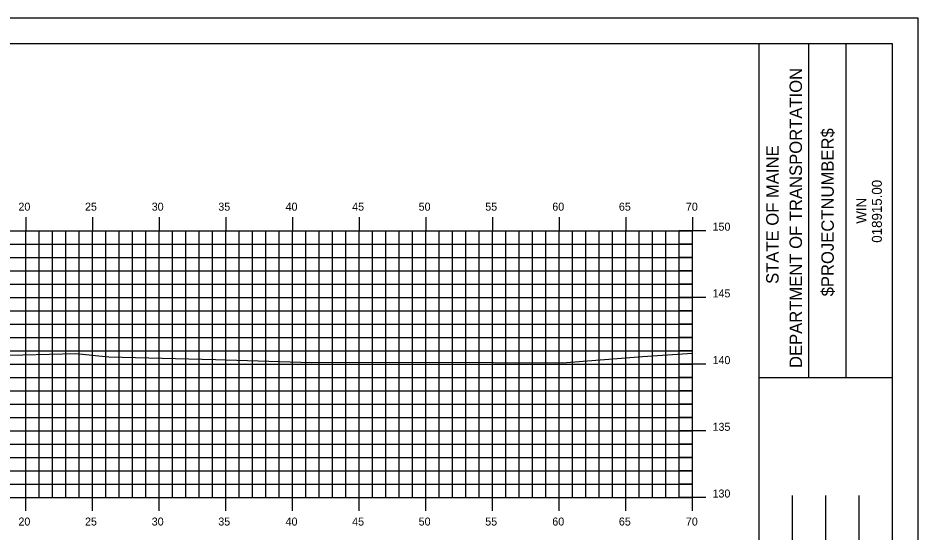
# Model space of a CAD drawing. Extents: x 851195 to 851367, y 365876 to 365986.
# Drawn here: x 851297.6 to 851365, y 365947.2 to 365985.8 of the extents above; entities that cross this region are included whole.
import ezdxf

# ---------------------------------------------------------------- set-up
doc = ezdxf.new("R2010")
doc.units = 0
for name, color, linetype in [('BORDER', 7, 'Continuous'), ('H_V ANNOTATION', 7, 'Continuous'), ('MAJOR', 7, 'Continuous'), ('MINOR', 7, 'Continuous'), ('PLOT BOUNDARY', 7, 'Continuous'), ('S_Roadway_Centerline', 7, 'Continuous')]:
    doc.layers.add(name, color=color, linetype=linetype)

msp = doc.modelspace()

# ---------------------------------------------------------------- linework, layer by layer
at = {"layer": 'BORDER'}
for p, q in [((851353.142, 365878.833), (851353.142, 365983.833)), ((851356.871, 365958.83), (851356.871, 365983.83)), ((851359.666, 365958.83), (851359.666, 365983.83)), ((851353.143, 365958.827), (851363.142, 365958.827)), ((851355.642, 365941.336), (851355.642, 365949.984)), ((851358.142, 365941.336), (851358.142, 365949.984)), ((851360.642, 365941.336), (851360.642, 365949.984))]:
    msp.add_line(p, q, dxfattribs=at)
msp.add_lwpolyline([(851203.142, 365878.833), (851363.142, 365878.833), (851363.142, 365983.833), (851203.142, 365983.833)], close=True, dxfattribs=at)
at = {"layer": 'MAJOR'}
for p, q in [((851298.142, 365970.835), (851298.142, 365969.833)), ((851303.142, 365970.835), (851303.142, 365969.833)), ((851308.142, 365970.835), (851308.142, 365969.833)), ((851313.142, 365970.835), (851313.142, 365969.833)), ((851318.142, 365970.835), (851318.142, 365969.833)), ((851323.142, 365970.835), (851323.142, 365969.833)), ((851328.142, 365970.835), (851328.142, 365969.833)), ((851333.142, 365970.835), (851333.142, 365969.833)), ((851338.142, 365970.835), (851338.142, 365969.833)), ((851343.142, 365970.835), (851343.142, 365969.833)), ((851348.142, 365970.835), (851348.142, 365969.833)), ((851208.142, 365969.833), (851348.142, 365969.833)), ((851208.142, 365969.833), (851348.142, 365969.833)), ((851298.142, 365949.833), (851298.142, 365969.833)), ((851303.142, 365949.833), (851303.142, 365969.833)), ((851308.142, 365949.833), (851308.142, 365969.833)), ((851313.142, 365949.833), (851313.142, 365969.833)), ((851318.142, 365949.833), (851318.142, 365969.833)), ((851323.142, 365949.833), (851323.142, 365969.833)), ((851328.142, 365949.833), (851328.142, 365969.833)), ((851333.142, 365949.833), (851333.142, 365969.833)), ((851338.142, 365949.833), (851338.142, 365969.833)), ((851343.142, 365949.833), (851343.142, 365969.833)), ((851349.144, 365969.833), (851347.14, 365969.833)), ((851348.142, 365949.833), (851348.142, 365969.833)), ((851348.142, 365949.833), (851348.142, 365969.833)), ((851208.142, 365964.833), (851348.142, 365964.833)), ((851349.144, 365964.833), (851347.14, 365964.833)), ((851208.142, 365959.833), (851348.142, 365959.833)), ((851349.144, 365959.833), (851347.14, 365959.833)), ((851208.142, 365954.833), (851348.142, 365954.833)), ((851349.144, 365954.833), (851347.14, 365954.833)), ((851208.142, 365949.833), (851348.142, 365949.833)), ((851208.142, 365949.833), (851348.142, 365949.833)), ((851298.142, 365948.831), (851298.142, 365949.833)), ((851303.142, 365948.831), (851303.142, 365949.833)), ((851308.142, 365948.831), (851308.142, 365949.833)), ((851313.142, 365948.831), (851313.142, 365949.833)), ((851318.142, 365948.831), (851318.142, 365949.833)), ((851323.142, 365948.831), (851323.142, 365949.833)), ((851328.142, 365948.831), (851328.142, 365949.833)), ((851333.142, 365948.831), (851333.142, 365949.833)), ((851338.142, 365948.831), (851338.142, 365949.833)), ((851343.142, 365948.831), (851343.142, 365949.833)), ((851349.144, 365949.833), (851347.14, 365949.833)), ((851348.142, 365948.831), (851348.142, 365949.833))]:
    msp.add_line(p, q, dxfattribs=at)
at = {"layer": 'MINOR'}
for p, q in [((851299.142, 365949.833), (851299.142, 365969.833)), ((851300.142, 365949.833), (851300.142, 365969.833)), ((851301.142, 365949.833), (851301.142, 365969.833)), ((851302.142, 365949.833), (851302.142, 365969.833)), ((851304.142, 365949.833), (851304.142, 365969.833)), ((851305.142, 365949.833), (851305.142, 365969.833)), ((851306.142, 365949.833), (851306.142, 365969.833)), ((851307.142, 365949.833), (851307.142, 365969.833)), ((851309.142, 365949.833), (851309.142, 365969.833)), ((851310.142, 365949.833), (851310.142, 365969.833)), ((851311.142, 365949.833), (851311.142, 365969.833)), ((851312.142, 365949.833), (851312.142, 365969.833)), ((851314.142, 365949.833), (851314.142, 365969.833)), ((851315.142, 365949.833), (851315.142, 365969.833)), ((851316.142, 365949.833), (851316.142, 365969.833)), ((851317.142, 365949.833), (851317.142, 365969.833)), ((851319.142, 365949.833), (851319.142, 365969.833)), ((851320.142, 365949.833), (851320.142, 365969.833)), ((851321.142, 365949.833), (851321.142, 365969.833)), ((851322.142, 365949.833), (851322.142, 365969.833)), ((851324.142, 365949.833), (851324.142, 365969.833)), ((851325.142, 365949.833), (851325.142, 365969.833)), ((851326.142, 365949.833), (851326.142, 365969.833)), ((851327.142, 365949.833), (851327.142, 365969.833)), ((851329.142, 365949.833), (851329.142, 365969.833)), ((851330.142, 365949.833), (851330.142, 365969.833)), ((851331.142, 365949.833), (851331.142, 365969.833)), ((851332.142, 365949.833), (851332.142, 365969.833)), ((851334.142, 365949.833), (851334.142, 365969.833)), ((851335.142, 365949.833), (851335.142, 365969.833)), ((851336.142, 365949.833), (851336.142, 365969.833)), ((851337.142, 365949.833), (851337.142, 365969.833)), ((851339.142, 365949.833), (851339.142, 365969.833)), ((851340.142, 365949.833), (851340.142, 365969.833)), ((851341.142, 365949.833), (851341.142, 365969.833)), ((851342.142, 365949.833), (851342.142, 365969.833)), ((851344.142, 365949.833), (851344.142, 365969.833)), ((851345.142, 365949.833), (851345.142, 365969.833)), ((851346.142, 365949.833), (851346.142, 365969.833)), ((851347.142, 365949.833), (851347.142, 365969.833)), ((851208.142, 365968.833), (851348.142, 365968.833)), ((851348.142, 365968.833), (851347.14, 365968.833)), ((851208.142, 365967.833), (851348.142, 365967.833)), ((851348.142, 365967.833), (851347.14, 365967.833)), ((851208.142, 365966.833), (851348.142, 365966.833)), ((851348.142, 365966.833), (851347.14, 365966.833)), ((851208.142, 365965.833), (851348.142, 365965.833)), ((851348.142, 365965.833), (851347.14, 365965.833)), ((851208.142, 365963.833), (851348.142, 365963.833)), ((851348.142, 365963.833), (851347.14, 365963.833)), ((851208.142, 365962.833), (851348.142, 365962.833)), ((851348.142, 365962.833), (851347.14, 365962.833)), ((851208.142, 365961.833), (851348.142, 365961.833)), ((851348.142, 365961.833), (851347.14, 365961.833)), ((851208.142, 365960.833), (851348.142, 365960.833)), ((851348.142, 365960.833), (851347.14, 365960.833)), ((851208.142, 365958.833), (851348.142, 365958.833)), ((851348.142, 365958.833), (851347.14, 365958.833)), ((851208.142, 365957.833), (851348.142, 365957.833)), ((851348.142, 365957.833), (851347.14, 365957.833)), ((851208.142, 365956.833), (851348.142, 365956.833)), ((851348.142, 365956.833), (851347.14, 365956.833)), ((851208.142, 365955.833), (851348.142, 365955.833)), ((851348.142, 365955.833), (851347.14, 365955.833)), ((851208.142, 365953.833), (851348.142, 365953.833)), ((851348.142, 365953.833), (851347.14, 365953.833)), ((851208.142, 365952.833), (851348.142, 365952.833)), ((851348.142, 365952.833), (851347.14, 365952.833)), ((851208.142, 365951.833), (851348.142, 365951.833)), ((851348.142, 365951.833), (851347.14, 365951.833)), ((851208.142, 365950.833), (851348.142, 365950.833)), ((851348.142, 365950.833), (851347.14, 365950.833))]:
    msp.add_line(p, q, dxfattribs=at)
at = {"layer": 'PLOT BOUNDARY'}
msp.add_lwpolyline([(851195.049, 365875.774), (851365.049, 365875.774), (851365.049, 365985.774), (851195.049, 365985.774)], close=True, dxfattribs=at)
at = {"layer": 'S_Roadway_Centerline'}
msp.add_lwpolyline([(851295.903, 365960.484), (851301.91, 365960.62), (851304.386, 365960.373), (851312.37, 365960.18), (851319.562, 365959.945), (851328.106, 365959.979), (851338.358, 365959.936), (851344.396, 365960.404), (851348.142, 365960.656)], dxfattribs=at)

# ---------------------------------------------------------------- texts
at = {"layer": 'BORDER'}
for s, height, p in [('DEPARTMENT OF TRANSPORTATION', 0.93176, (851356.349, 365959.539)), ('$PROJECTNUMBER$', 0.93176, (851358.734, 365964.912)), ('STATE OF MAINE', 0.93176, (851354.597, 365965.845)), ('018915.00', 0.7453, (851362.338, 365968.931)), ('WIN', 0.7453, (851361.179, 365970.363))]:
    msp.add_text(s, height=height, rotation=90, dxfattribs=at).set_placement(p)
at = {"layer": 'H_V ANNOTATION'}
for s, p in [('20', (851297.596, 365971.333)), ('25', (851302.588, 365971.333)), ('30', (851307.591, 365971.333)), ('35', (851312.583, 365971.333)), ('40', (851317.628, 365971.333)), ('45', (851322.62, 365971.333)), ('50', (851327.607, 365971.333)), ('55', (851332.599, 365971.333)), ('60', (851337.628, 365971.333)), ('65', (851342.62, 365971.333)), ('70', (851347.644, 365971.333)), ('150', (851349.642, 365969.833)), ('145', (851349.642, 365964.833)), ('140', (851349.642, 365959.833)), ('135', (851349.642, 365954.833)), ('130', (851349.642, 365949.833)), ('20', (851297.596, 365947.733)), ('25', (851302.588, 365947.733)), ('30', (851307.591, 365947.733)), ('35', (851312.583, 365947.733)), ('40', (851317.628, 365947.733)), ('45', (851322.62, 365947.733)), ('50', (851327.607, 365947.733)), ('55', (851332.599, 365947.733)), ('60', (851337.628, 365947.733)), ('65', (851342.62, 365947.733)), ('70', (851347.644, 365947.733))]:
    msp.add_text(s, height=0.6, dxfattribs=at).set_placement(p)

doc.saveas('drawing.dxf')
